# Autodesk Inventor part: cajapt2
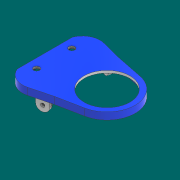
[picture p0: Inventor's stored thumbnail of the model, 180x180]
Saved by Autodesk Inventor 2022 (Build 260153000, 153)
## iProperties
Created: 2021-11
Part Number: cajapt2
Material: Generic
Document SubType Name: Modeling
Designer: santi
Density: 1 g/cm^3
Appearance: Default
Author: santi
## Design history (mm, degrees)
sketch "Sketch1"
  geometry: C1 r 21 at (0, 0); C2 r 20 at (0, 0); 1 further point
  constraints: 2 centre point, 1 coincident
  dimensions: "d0" = 42 diameter of C1; "d1" = 1 radial gap between concentric circles of C1 C2
extrude "Extrusion1" new body sketch "Sketch1" distance "d2" = 15; taper "d3" = 0 deg
sketch "Sketch2" dims "d4" = 48
  geometry: L1 (-24, 0)-(-24, 5.5); L2 (-24, 5.5)-(-24, -5.5); L3 (-24, -5.5)-(-20.267, -5.5); L4 (-24, 5.5)-(-20.267, 5.5); L5 (0, 0)-(0, 10.729); L6 (24, 0)-(24, 5.5); L7 (24, 5.5)-(24, -5.5); L8 (24, -5.5)-(20.267, -5.5); L9 (24, 5.5)-(20.267, 5.5); L10 (23, 5.5)-(23, -4.5); L11 (23, -4.5)-(20.267, -4.5); L12 (24, 4.5)-(20.267, 4.5); L13 (-23, 5.5)-(-23, -4.5); L14 (-23, -4.5)-(-20.267, -4.5); L15 (-24, 4.5)-(-20.267, 4.5); C1 r 21 at (0, 0) reference; C2 r 23 at (0, 0); C3 r 21 at (0, 0); C4 r 23 at (0, 0); A1 r 21 centre (0, 0) between (-20.267, -5.5) and (-20.267, 5.5) reference; A2 r 21 centre (0, 0) between (20.267, -5.5) and (20.267, 5.5); 16 further points
  constraints: 30 end point, 5 symmetric about line, 4 centre point, 4 point on circle, 4 vertical, 2 coincident, 2 parallel, 2 perpendicular, 2 point on line, 1 horizontal alignment, 10 other
  dimensions: "d5" = 1 dimension on C2; "d6" = 5.5 distance of L1.start L1.end; "d7" = 11 distance of L1.end L2.end; "d8" = 1 distance between parallel lines of L7 L10; "d9" = 1 distance between parallel lines of L9 L12; "d10" = 1 distance between parallel lines of L2 L13; "d11" = 1 distance between parallel lines of L4 L15
extrude "Extrusion2" join sketch "Sketch2" distance "d12" = 15; taper "d13" = 0 deg
sketch "Sketch3"
  geometry: L1 (-20.512, 4.5)-(20.512, 4.5); L2 (-20.512, -4.5)-(20.512, -4.5); A1 r 21 centre (0, 0) between (-20.512, 4.5) and (-20.512, -4.5) reference; A2 r 21 centre (0, 0) between (20.512, -4.5) and (20.512, 4.5) reference; A3 r 21 centre (0, 0) between (20.512, -4.5) and (20.512, 4.5) reference; 1 further point
  constraints: 4 end point, 2 horizontal
extrude "Extrusion3" cut sketch "Sketch3" distance "d14" = 15; taper "d15" = 0 deg
workplane "Work Plane1"
sketch "Sketch4"
  geometry: C1 r 15 at (0, 0); 1 further point
  constraints: 1 centre point, 1 coincident
  dimensions: "d17" = 30 diameter of C1
sketch "Sketch5"
  geometry: L1 (-24, -5.5)-(-20.267, -5.5) reference; L2 (-24, 5.5)-(-24, -5.5) reference; L3 (-20.267, 5.5)-(-24, 5.5) reference; L4 (23.361, 5.5)-(20.267, 5.5) reference; L5 (20.267, -5.5)-(23.361, -5.5) reference; A1 r 21 centre (0, 0) between (-20.267, -5.5) and (20.267, -5.5) reference; A2 r 21 centre (0, 0) between (20.267, 5.5) and (-20.267, 5.5) reference; A3 r 24 centre (0, 0) between (23.361, -5.5) and (23.361, 5.5) reference; 1 further point
loft "Loft1" dims "d18" = 0, "d19" = 90 deg, "d20" = 0, "d21" = 90 deg
  node "Edges1"
sketch "Sketch6"
  geometry: C1 r 6.5 at (0, 0); C2 r 5.5 at (0, 0); 1 further point
  constraints: 2 centre point, 1 coincident
  dimensions: "d22" = 13 diameter of C1; "d23" = 1 radial gap between concentric circles of C1 C2
extrude "Extrusion4" join sketch "Sketch6" distance "d24" = 2; taper "d25" = 0 deg
sketch "Sketch7"
  geometry: C1 r 5.5 at (0, 0) reference; 1 further point
extrude "Extrusion5" cut sketch "Sketch7" distance "d26" = 6; taper "d27" = 0 deg
sketch "Sketch8"
  geometry: L1 (-20.19, 4.5)-(-20.19, -5.5); L2 (-20.19, -5.5)-(-20.19, 14.5); C1 r 2.5 at (-20.19, 14.5); C2 r 2.5 at (-20.19, -5.5)
  constraints: 4 end point, 2 centre point, 2 coincident, 1 point on line, 1 vertical
  dimensions: "d28" = 10 distance of L1.start L1.end; "d29" = 20 distance of L1.end L2.end; "d30" = 5 diameter of C1; "d31" = 5 diameter of C2
extrude "Extrusion6" cut sketch "Sketch8" distance "d32" = 10; taper "d33" = 0 deg
workplane "Work Plane2"
sketch "Sketch9"
  geometry: L1 (-20.206, 4.5)-(-22.555, 4.5) reference; L2 (-22.555, -4.5)-(-20.605, -4.5) reference; L3 (-20.605, -4.5)-(-19.487, -4.5) reference; L4 (19.487, -4.5)-(20.19, -4.5) reference; L5 (20.19, -4.5)-(22.555, -4.5) reference; L6 (22.555, 4.5)-(20.206, 4.5) reference; L7 (20.206, 4.5)-(19.487, 4.5) reference; L8 (-19.487, 4.5)-(-20.206, 4.5) reference; L9 (18.675, 3.5)-(21.72, 3.5); L10 (21.72, -3.5)-(20.19, -3.5); L11 (20.19, -3.5)-(18.675, -3.5); L12 (-18.675, -3.5)-(-20.605, -3.5); L13 (-20.605, -3.5)-(-21.72, -3.5); L14 (-21.72, 3.5)-(-18.675, 3.5); C1 r 2.5 at (0, -10) reference; C2 r 2.5 at (0, 10) reference; A1 r 23 centre (0, 0) between (-22.555, 4.5) and (-22.555, -4.5) reference; A2 r 20 centre (0, 0) between (-19.487, -4.5) and (19.487, -4.5) reference; A3 r 23 centre (0, 0) between (22.555, -4.5) and (22.555, 4.5) reference; A4 r 20 centre (0, 0) between (19.487, 4.5) and (-19.487, 4.5) reference; A5 r 19 centre (0, 0) between (18.675, 3.5) and (-18.675, 3.5); A6 r 22 centre (0, 0) between (21.72, -3.5) and (21.72, 3.5); A7 r 19 centre (0, 0) between (-18.675, -3.5) and (18.675, -3.5); A8 r 22 centre (0, 0) between (-21.72, 3.5) and (-21.72, -3.5); 1 further point
  constraints: 12 end point, 8 point on circle, 4 centre point, 9 other
  dimensions: "d35" = 1 radial gap between concentric circles of A4 A5
extrude "Extrusion7" join sketch "Sketch9" distance "d36" = 17; taper "d37" = 0 deg
sketch "Sketch10"
  geometry: L1 (39.295, -21.094)-(-36.743, -21.094); L2 (-36.743, -21.094)-(-30.463, 43.655); L3 (-30.463, 43.655)-(40.715, 44.776); L4 (40.715, 44.776)-(39.295, -21.094); 1 further point
  constraints: 8 end point, 1 horizontal
extrude "Extrusion8" cut sketch "Sketch10" distance "d38" = 50; taper "d39" = 0 deg
sketch "Sketch11"
  geometry: C1 r 2.5 at (0, -10) reference; C2 r 2.5 at (0, 10) reference; 1 further point
extrude "Extrusion9" join sketch "Sketch11" stored distance "d40" = 34; taper "d41" = 0 deg
fillet "Fillet1" dims "d42" = 2.5
sketch "Sketch12"
  geometry: L1 (0, 21.5)-(-10.665, 21.5); L2 (0, -21.5)-(-10.665, -21.5); A1 r 21.5 centre (0, 0) between (0, 21.5) and (0, -21.5); A2 r 24 centre (0, 0) between (-10.665, 21.5) and (-10.665, -21.5); 1 further point
  constraints: 4 end point, 4 point on circle, 2 centre point, 2 coincident, 1 horizontal, 1 parallel, 1 tangent
  dimensions: "d43" = 43 diameter of A1; "d44" = 48 diameter of A2
extrude "Extrusion10" join sketch "Sketch12" distance "d45" = 2; taper "d46" = 0 deg
sketch "Sketch13"
  geometry: L1 (-24, 0)-(-24, -31); L2 (-24, -31)-(-24, 31); L3 (-24, 31)-(7.019, 22.951); L4 (-24, -31)-(6.012, -23.235); A1 r 24 centre (0, 0) between (-10.665, 21.5) and (-10.665, -21.5) reference; A2 r 24 centre (0, 0) between (-10.665, 21.5) and (-10.665, -21.5) reference; A3 r 24 centre (0, 0) between (7.019, 22.951) and (6.012, -23.235); 2 further points
  constraints: 8 end point, 4 point on circle, 2 tangent, 1 centre point, 1 coincident, 1 point on line, 1 vertical
  dimensions: "d47" = 31 distance of L1.start L1.end; "d48" = 62 distance of L1.end L2.end
extrude "Extrusion11" join sketch "Sketch13" distance "d49" = 2; taper "d50" = 0 deg
fillet "Fillet2" dims "d51" = 10
sketch "Sketch14"
  geometry: L1 (0, 1.38)-(-17.471, 1.38); L2 (-17.471, 1.38)-(-17.471, -1.312); L3 (-17.471, -1.312)-(0, -1.312); L4 (0, -1.312)-(0, 1.38); L5 (15.996, -4.2)-(5.478, -4.2); L6 (5.478, -4.2)-(5.478, -6.53); L7 (5.478, -6.53)-(15.996, -6.53); L8 (15.996, -6.53)-(15.996, -4.2); L9 (15.996, 7.583)-(5.478, 7.583); L10 (5.478, 7.583)-(5.478, 3.655); L11 (5.478, 3.655)-(15.996, 3.655); L12 (15.996, 3.655)-(15.996, 7.583); 1 further point
  constraints: 24 end point, 6 parallel, 3 horizontal, 3 perpendicular, 2 point on line
extrude "Extrusion12" cut sketch "Sketch14" distance "d52" = 2; taper "d53" = 0 deg
workplane "Work Plane3"
sketch "Sketch15"
  geometry: L1 (21.72, -3.5)-(18.675, -3.5) reference; L2 (18.675, 3.5)-(21.72, 3.5) reference; L3 (-21.72, 3.5)-(-18.675, 3.5) reference; L4 (-18.675, -3.5)-(-21.72, -3.5) reference; L5 (21.018, 6.5)-(24.14, 6.5); L6 (24.14, -6.5)-(21.018, -6.5); L7 (-21.018, -6.5)-(-24.14, -6.5); L8 (-24.14, 6.5)-(-21.018, 6.5); C1 r 2.5 at (0, -10) reference; C2 r 2.5 at (0, 10) reference; A1 r 19 centre (0, 0) between (-18.675, -3.5) and (18.675, -3.5) reference; A2 r 22 centre (0, 0) between (21.72, -3.5) and (21.72, 3.5) reference; A3 r 19 centre (0, 0) between (18.675, 3.5) and (-18.675, 3.5) reference; A4 r 22 centre (0, 0) between (-21.72, 3.5) and (-21.72, -3.5) reference; A5 r 19 centre (0, 0) between (-18.675, -3.5) and (18.675, -3.5) reference; A6 r 22 centre (0, 0) between (21.018, 6.5) and (-21.018, 6.5); A7 r 25 centre (0, 0) between (24.14, -6.5) and (24.14, 6.5); A8 r 22 centre (0, 0) between (-21.018, -6.5) and (21.018, -6.5); A9 r 25 centre (0, 0) between (-24.14, 6.5) and (-24.14, -6.5); 3 further points
  constraints: 8 end point, 8 point on circle, 4 centre point, 7 other
  dimensions: "d55" = 3 radial gap between concentric circles of A3 A6
extrude "Extrusion13" join sketch "Sketch15" distance "d56" = 2; taper "d57" = 0 deg
sketch "Sketch16"
  geometry: L1 (-25, 0)-(-25, 30); L2 (-25, 0)-(-25, -30); L3 (-11.495, 27.765)-(6.012, 23.235) reference; L4 (7.019, -22.951)-(-11.488, -27.753) reference; L5 (-10.994, 29.701)-(6.513, 25.171); L6 (7.522, -24.886)-(-10.986, -29.689); L7 (6.513, 25.171)-(29.169, 20.582); L8 (7.522, -24.886)-(29.095, -20.597); L9 (-10.994, 29.701)-(6.513, 25.171); L10 (-10.986, -29.689)-(7.522, -24.886); L11 (24.14, 6.5)-(21.018, 6.5) reference; L12 (-21.018, 6.5)-(-24.14, 6.5) reference; L13 (-24.14, -6.5)-(-21.018, -6.5) reference; L14 (21.018, -6.5)-(24.14, -6.5) reference; L15 (21.72, -3.5)-(18.675, -3.5) reference; L16 (-18.675, -3.5)-(-21.72, -3.5) reference; L17 (-21.72, 3.5)-(-18.675, 3.5) reference; L18 (18.675, 3.5)-(21.72, 3.5) reference; A1 r 25 centre (0, 0) between (-24.14, 6.5) and (-24.14, -6.5) reference; A2 r 25 centre (0, 0) between (24.14, -6.5) and (24.14, 6.5) reference; A3 r 25 centre (0, 0) between (24.14, -6.5) and (24.14, 6.5) reference; A4 r 21 centre (25, 0) between (29.095, -20.597) and (29.169, 20.582); A5 r 10 centre (-14, 18.083) between (-11.495, 27.765) and (-24, 18.083) reference; A6 r 12 centre (-14, 18.083) between (-10.994, 29.701) and (-25, 22.879); A7 r 10 centre (-14, -18.074) between (-24, -18.074) and (-11.488, -27.753) reference; A8 r 12 centre (-14, -18.074) between (-25, -22.87) and (-10.986, -29.689); A9 r 22 centre (0, 0) between (21.018, 6.5) and (-21.018, 6.5) reference; A10 r 25 centre (0, 0) between (-24.14, 6.5) and (-24.14, -6.5) reference; A11 r 22 centre (0, 0) between (-21.018, -6.5) and (21.018, -6.5) reference; A12 r 25 centre (0, 0) between (24.14, -6.5) and (24.14, 6.5) reference; A13 r 19 centre (0, 0) between (-18.675, -3.5) and (18.675, -3.5) reference; A14 r 22 centre (0, 0) between (-21.72, 3.5) and (-21.72, -3.5) reference; A15 r 19 centre (0, 0) between (18.675, 3.5) and (-18.675, 3.5) reference; A16 r 22 centre (0, 0) between (21.72, -3.5) and (21.72, 3.5) reference; 7 further points
  constraints: 16 end point, 9 point on circle, 4 tangent, 3 centre point, 2 parallel, 2 point on line, 2 vertical
  dimensions: "d58" = 30 distance of L1.start L1.end; "d59" = 30 distance of L1.start L2.end; "d60" = 42 diameter of A4; "d61" = 2 distance between parallel lines of L3 L5; "d62" = 2 distance between parallel lines of L4 L6; "d63" = 2 radial gap between concentric circles of A5 A6; "d64" = 2 radial gap between concentric circles of A7 A8
extrude "Extrusion14" join sketch "Sketch16" distance "d65" = 2; taper "d66" = 0 deg
sketch "Sketch17"
  geometry: L1 (0, 1.312)-(-17.471, 1.312) reference; L2 (-17.471, 1.312)-(-17.471, -1.38) reference; L3 (-17.471, -1.38)-(0, -1.38) reference; L4 (0, -1.38)-(0, 1.312) reference; L5 (-11.495, 27.765)-(6.012, 23.235) reference; L6 (7.019, -22.951)-(-11.488, -27.753) reference; L7 (-24, -18.074)-(-24, 18.083) reference; L8 (0, 1.312)-(-17.471, 1.312) reference; L9 (0, 1.312)-(-17.471, 1.312) reference; A1 r 10 centre (-14, 18.083) between (-11.495, 27.765) and (-24, 18.083) reference; A2 r 24 centre (0, 0) between (7.019, -22.951) and (6.012, 23.235) reference; A3 r 10 centre (-14, -18.074) between (-24, -18.074) and (-11.488, -27.753) reference; 1 further point
extrude "Extrusion15" cut sketch "Sketch17" distance "d67" = 55; taper "d68" = 0 deg
sketch "Sketch18"
  geometry: L1 (-25, 22.87)-(-25, -22.879) reference; L2 (7.522, 24.886)-(-10.986, 29.689) reference; L3 (29.095, 20.597)-(7.522, 24.886) reference; L4 (6.513, -25.171)-(29.169, -20.582) reference; L5 (-10.994, -29.701)-(6.513, -25.171) reference; L6 (-10.243, -32.605)-(7.187, -28.096); L7 (7.187, -28.096)-(29.765, -23.522); L8 (29.68, 23.539)-(8.192, 27.812); L9 (8.192, 27.812)-(-10.232, 32.593); L10 (-28, 23.459)-(-28, -23.468); A1 r 12 centre (-14, -18.083) between (-25, -22.879) and (-10.994, -29.701) reference; A2 r 12 centre (-14, 18.074) between (-10.986, 29.689) and (-25, 22.87) reference; A3 r 21 centre (25, 0) between (29.169, -20.582) and (29.095, 20.597) reference; A4 r 15 centre (-14, -18.083) between (-28, -23.468) and (-10.243, -32.605); A5 r 24 centre (25, 0) between (29.765, -23.522) and (29.68, 23.539); A6 r 15 centre (-14, 18.074) between (-10.232, 32.593) and (-28, 23.459); 1 further point
  constraints: 10 end point, 6 point on circle, 3 centre point, 7 other
  dimensions: "d69" = 3 distance between parallel lines of L1 L10
extrude "Extrusion16" join sketch "Sketch18" distance "d70" = 2; taper "d71" = 0 deg
sketch "Sketch19"
  geometry: L1 (8.192, 27.812)-(-10.232, 32.593) reference; L2 (29.68, 23.539)-(8.192, 27.812) reference; L3 (7.187, -28.096)-(29.765, -23.522) reference; L4 (-10.243, -32.605)-(7.187, -28.096) reference; L5 (-28, 23.459)-(-28, -23.468) reference; L6 (-10.735, 30.657)-(7.745, 25.862); L7 (7.745, 25.862)-(29.29, 21.578); L8 (29.367, -21.562)-(6.737, -26.146); L9 (6.737, -26.146)-(-10.744, -30.669); L10 (-26, -23.083)-(-26, 23.074); A1 r 15 centre (-14, 18.074) between (-10.232, 32.593) and (-28, 23.459) reference; A2 r 24 centre (25, 0) between (29.765, -23.522) and (29.68, 23.539) reference; A3 r 15 centre (-14, -18.083) between (-28, -23.468) and (-10.243, -32.605) reference; A4 r 13 centre (-14, 18.074) between (-10.735, 30.657) and (-26, 23.074); A5 r 22 centre (25, 0) between (29.367, -21.562) and (29.29, 21.578); A6 r 13 centre (-14, -18.083) between (-26, -23.083) and (-10.744, -30.669); 1 further point
  constraints: 10 end point, 6 point on circle, 3 centre point, 7 other
  dimensions: "d72" = 2 radial gap between concentric circles of A1 A4
extrude "Extrusion17" join sketch "Sketch19" distance "d73" = 4; taper "d74" = 0 deg
sketch "Sketch20"
  geometry: L1 (7.187, 28.096)-(-10.243, 32.605) reference; L2 (-28, 23.468)-(-28, -23.459) reference; L3 (-10.232, -32.593)-(8.192, -27.812) reference; L4 (8.192, -27.812)-(29.68, -23.539) reference; L5 (29.765, 23.522)-(7.187, 28.096) reference; L6 (21.72, -3.5)-(18.675, -3.5) reference; L7 (-18.675, -3.5)-(-21.72, -3.5) reference; L8 (-21.72, 3.5)-(-18.675, 3.5) reference; L9 (18.675, 3.5)-(21.72, 3.5) reference; A1 r 15 centre (-14, 18.083) between (-10.243, 32.605) and (-28, 23.468) reference; A2 r 15 centre (-14, -18.074) between (-28, -23.459) and (-10.232, -32.593) reference; A3 r 24 centre (25, 0) between (29.68, -23.539) and (29.765, 23.522) reference; A4 r 19 centre (0, 0) between (-18.675, -3.5) and (18.675, -3.5) reference; A5 r 22 centre (0, 0) between (-21.72, 3.5) and (-21.72, -3.5) reference; A6 r 19 centre (0, 0) between (18.675, 3.5) and (-18.675, 3.5) reference; A7 r 22 centre (0, 0) between (21.72, -3.5) and (21.72, 3.5) reference; 1 further point
extrude "Extrusion18" join sketch "Sketch20" distance "d75" = 2; taper "d76" = 0 deg
sketch "Sketch21"
  geometry: C1 r 19.5 at (25, 0); A1 r 24 centre (25, 0) between (29.68, -23.539) and (29.765, 23.522) reference; 1 further point
  constraints: 1 centre point, 1 coincident
  dimensions: "d77" = 39 diameter of C1
extrude "Extrusion19" cut sketch "Sketch21" distance "d78" = 2; taper "d79" = 0 deg
sketch "Sketch22"
  geometry: L1 (0, 0)-(-20, 0); L2 (-20, 0)-(-20, -15); L3 (-20, -15)-(-20, 15); C1 r 2.5 at (-20, 15); C2 r 2.5 at (-20, -15)
  constraints: 6 end point, 2 centre point, 2 coincident, 1 horizontal, 1 perpendicular, 1 point on line
  dimensions: "d80" = 20 distance of L1.start L1.end; "d81" = 15 distance of L1.end L2.end; "d82" = 30 distance of L2.end L3.end; "d83" = 5 diameter of C1; "d84" = 5 diameter of C2
extrude "Extrusion20" cut sketch "Sketch22" distance "d85" = 4; taper "d86" = 0 deg
sketch "Sketch23"
  geometry: L1 (19.092, 0)-(0, 0) reference; L2 (0, 4)-(19.092, 4) reference; L3 (0, 4)-(0, 0) reference; L4 (19.092, 0)-(0, 0) reference; L5 (19.092, 4)-(19.092, 0) reference; L6 (9.546, 0)-(9.546, -5); L7 (4.546, -5)-(4.546, 0); L8 (14.546, -5)-(14.546, 0); L9 (14.546, 0)-(4.546, 0); L10 (-12.088, 0)-(3.697, 0) reference; A1 r 5 centre (9.546, -5) between (9.546, 0) and (4.546, -5); 3 further points
  constraints: 8 end point, 3 point on circle, 2 perpendicular, 2 point on line, 1 centre point, 1 coincident, 1 collinear, 1 midpoint, 1 vertical
  dimensions: "d87" = 5 distance of L6.start L6.end
extrude "Extrusion21" join sketch "Sketch23" distance "d88" = 3; taper "d89" = 0 deg
sketch "Sketch24"
  geometry: L1 (0, 4)-(19.092, 4) reference; L2 (14.546, 0)-(4.546, 0) reference; L3 (4.546, 0)-(4.546, 4); L4 (14.546, 0)-(14.546, 4); L5 (4.546, 4)-(14.546, 4); 1 further point
  constraints: 6 end point, 2 perpendicular, 2 point on line, 1 collinear
extrude "Extrusion22" join sketch "Sketch24" distance "d90" = 3; taper "d91" = 0 deg
sketch "Sketch25"
  geometry: L1 (18.057, 0)-(0, 0) reference; L2 (9.028, 0)-(9.028, -5); L3 (0, 4)-(18.057, 4) reference; L4 (14.028, -5)-(14.028, 4); L5 (4.028, -5)-(4.028, 4); L6 (14.028, 4)-(4.028, 4); A1 r 5 centre (9.028, -5) between (14.028, -5) and (4.028, -5); 1 further point
  constraints: 8 end point, 3 perpendicular, 2 point on circle, 2 point on line, 1 centre point, 1 coincident, 1 midpoint, 1 vertical
  dimensions: "d92" = 5 distance of L2.start L2.end; "d93" = 10 diameter of A1
extrude "Extrusion23" join sketch "Sketch25" distance "d94" = 3; taper "d95" = 0 deg
sketch "Sketch26"
  geometry: C1 r 1.5 at (9.028, -5); A1 r 5 centre (9.028, -5) between (4.028, -5) and (14.028, -5) reference; 1 further point
  constraints: 1 centre point, 1 coincident
  dimensions: "d96" = 3 diameter of C1
extrude "Extrusion24" cut sketch "Sketch26" distance "d97" = 3; taper "d98" = 0 deg
sketch "Sketch27"
  geometry: C1 r 1.5 at (-9.546, -5); A1 r 5 centre (-9.546, -5) between (-14.546, -5) and (-4.546, -5) reference; 1 further point
  constraints: 1 centre point, 1 coincident
  dimensions: "d99" = 3 diameter of C1
extrude "Extrusion25" cut sketch "Sketch27" distance "d100" = 3; taper "d101" = 0 deg
body "Solid1"
node "Projected Loop1"
node "Projected Loop2"
node "Projected Loop3"
node "Projected Loop4"
node "Projected Loop5"
node "Projected Loop6"
node "Projected Loop7"
node "Projected Loop8"
